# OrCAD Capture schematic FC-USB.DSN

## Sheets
1 INDEX: size A; title: INDEX; rev: 1.1; note: 188Z10031
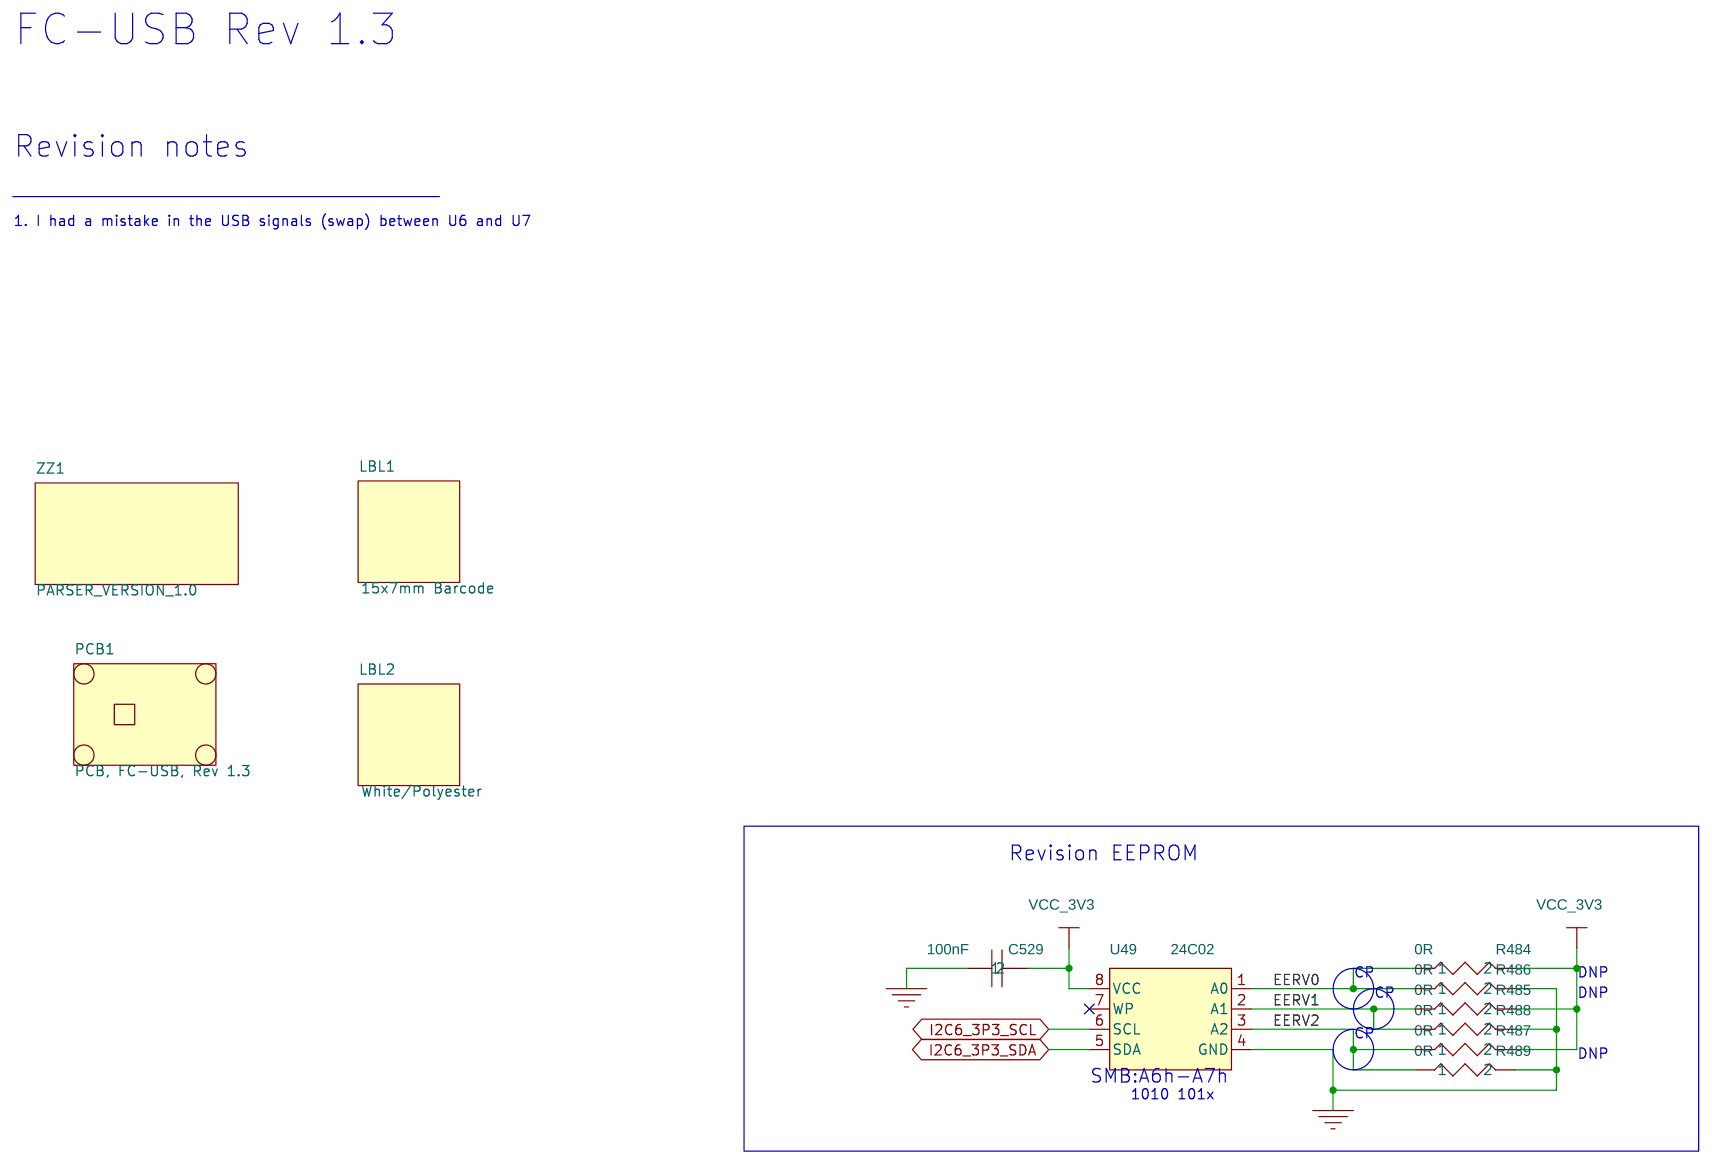
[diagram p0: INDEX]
2 M.2 WIFI+BT: size Custom; title: M.2 WIFI+BT
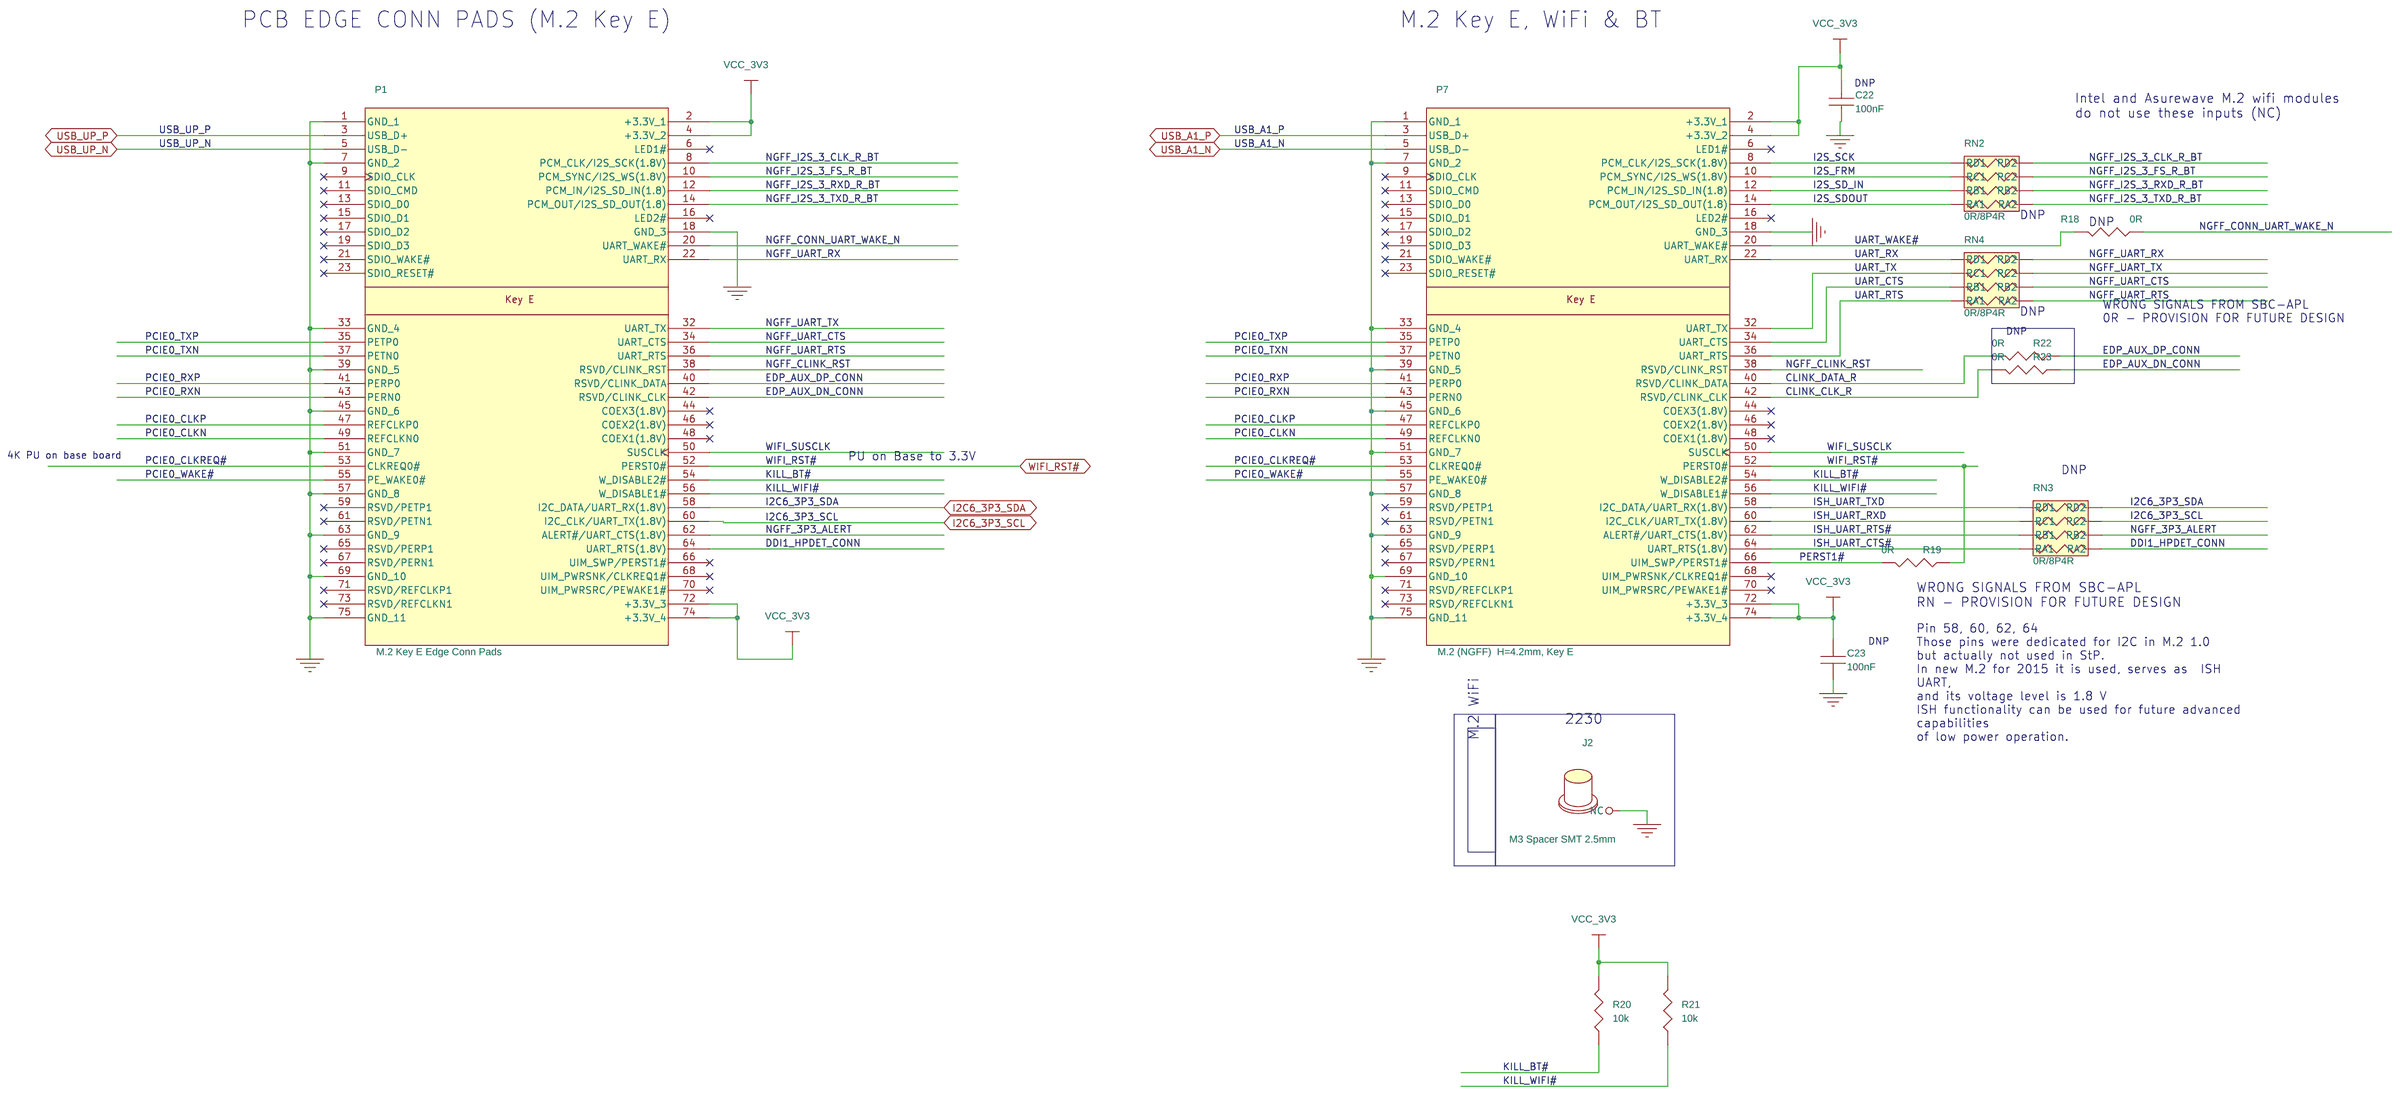
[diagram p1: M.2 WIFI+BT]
3 USB: size Custom; title: USB
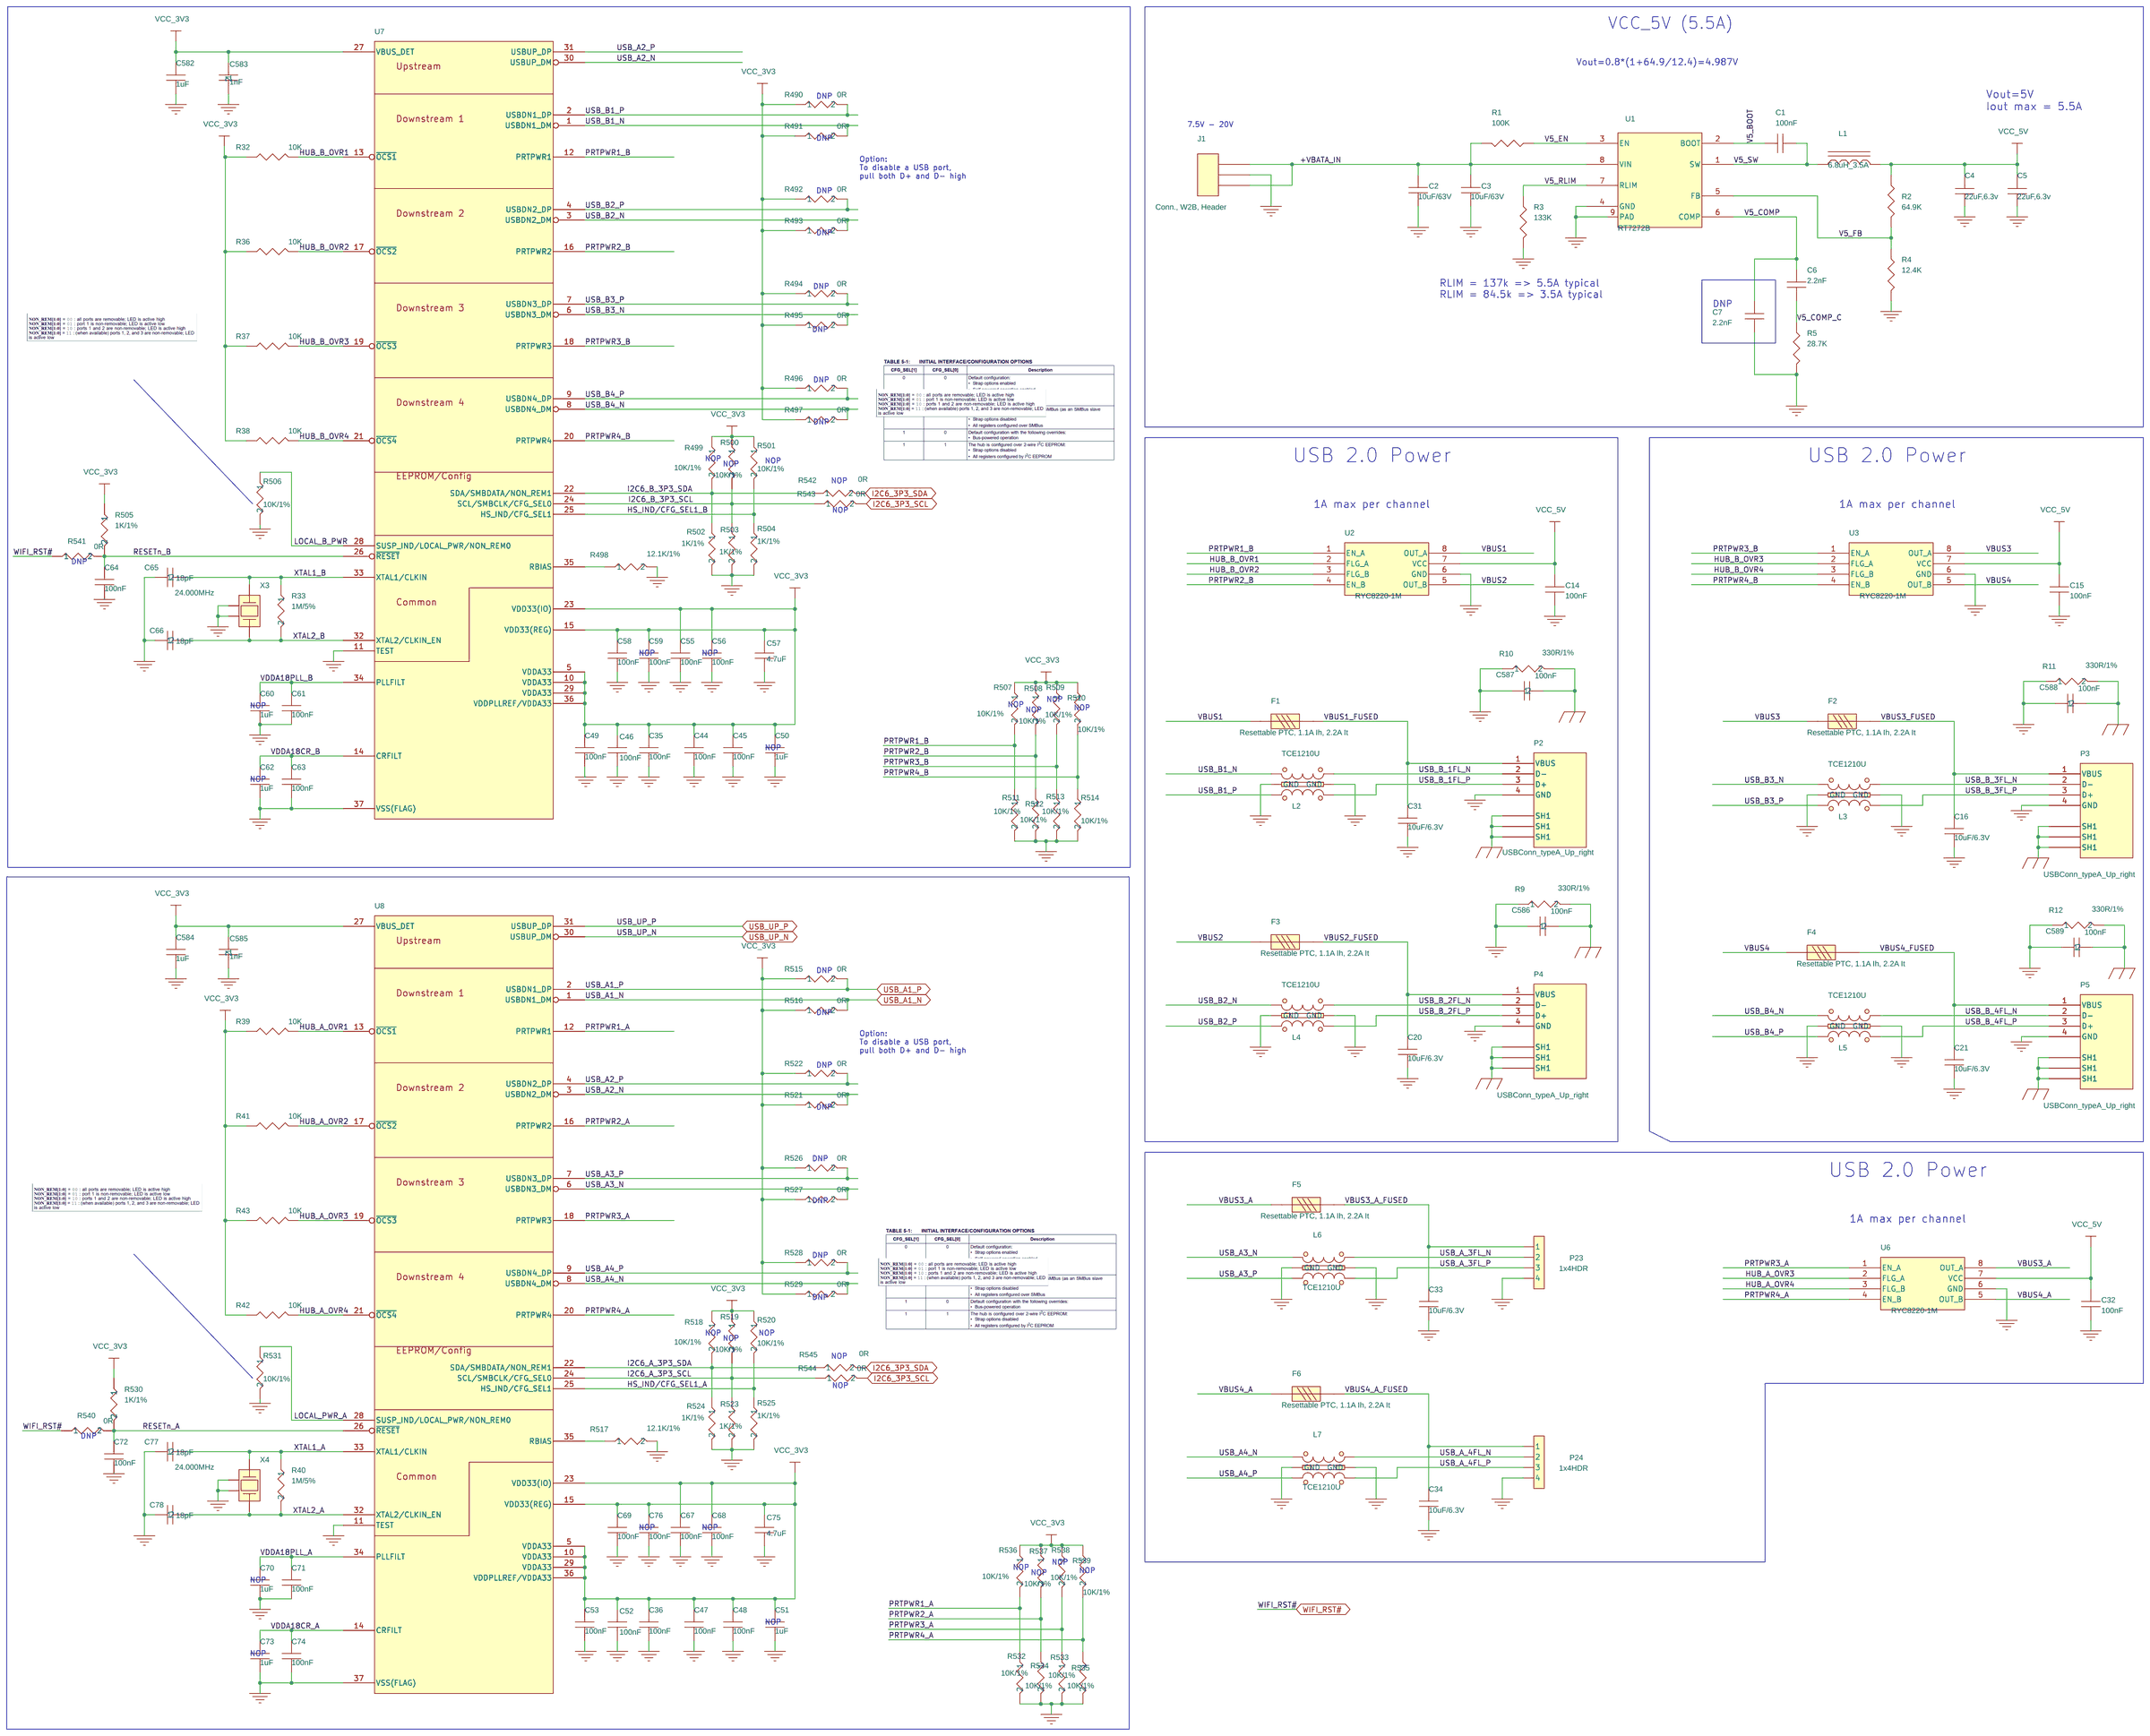
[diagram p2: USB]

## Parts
sheet INDEX
C529  100nF  [RC0402]
LBL1  15x7mm Barcode  [LBL XYU]
LBL2  White/Polyester  [LBL]
PCB1  PCB, FC-USB, Rev 1.3  [NA]
R484  0R  [RC0402]
R485  0R  [RC0402]
R486  0R  [RC0402]
R487  0R  [RC0402]
R488  0R  [RC0402]
R489  0R  [RC0402]
U49  24C02  [MO-229VCED-2]
ZZ1  PARSER_VERSION_1.0
sheet M.2 WIFI+BT
C22  100nF  [RC0402]
C23  100nF  [RC0402]
J2  M3 Spacer SMT 2.5mm  [SpacerM3TAPSM]
P1  M.2 Key E Edge Conn Pads  [EdgeM2keyE]
P7  M.2 (NGFF)  H=4.2mm, Key E  [NGFF67P4HEkeySM]
R18  0R  [RC0402]
R19  0R  [RC0402]
R20  10k  [RC0402]
R21  10k  [RC0402]
R22  0R  [RC0402]
R23  0R  [RC0402]
RN2  0R/8P4R  [RESNET8P0805]
RN3  0R/8P4R  [RESNET8P0805]
RN4  0R/8P4R  [RESNET8P0805]
sheet USB
C1  100nF  [RC0402]
C2  10uF/63V  [C1210H2_5]
C3  10uF/63V  [C1210H2_5]
C4  22uF,6.3v  [RC0603]
C5  22uF,6.3v  [RC0603]
C6  2.2nF  [RC0402]
C7  2.2nF  [RC0402]
C14  100nF  [RC0402]
C15  100nF  [RC0402]
C16  10uF/6.3V  [RC0603]
C20  10uF/6.3V  [RC0603]
C21  10uF/6.3V  [RC0603]
C31  10uF/6.3V  [RC0603]
C32  100nF  [RC0402]
C33  10uF/6.3V  [RC0603]
C34  10uF/6.3V  [RC0603]
C35  100nF  [RC0402]
C36  100nF  [RC0402]
C44  100nF  [RC0402]
C45  100nF  [RC0402]
C46  100nF  [RC0402]
C47  100nF  [RC0402]
C48  100nF  [RC0402]
C49  100nF  [RC0402]
C50  1uF  [RC0402]
C51  1uF  [RC0402]
C52  100nF  [RC0402]
C53  100nF  [RC0402]
C55  100nF  [RC0402]
C56  100nF  [RC0402]
C57  4.7uF  [C0603-08]
C58  100nF  [RC0402]
C59  100nF  [RC0402]
C60  1uF  [RC0402]
C61  100nF  [RC0402]
C62  1uF  [RC0402]
C63  100nF  [RC0402]
C64  100nF  [RC0402]
C65  18pF  [RC0402]
C66  18pF  [RC0402]
C67  100nF  [RC0402]
C68  100nF  [RC0402]
C69  100nF  [RC0402]
C70  1uF  [RC0402]
C71  100nF  [RC0402]
C72  100nF  [RC0402]
C73  1uF  [RC0402]
C74  100nF  [RC0402]
C75  4.7uF  [C0603-08]
C76  100nF  [RC0402]
C77  18pF  [RC0402]
C78  18pF  [RC0402]
C582  1uF  [RC0402]
C583  1nF  [RC0402]
C584  1uF  [RC0402]
C585  1nF  [RC0402]
C586  100nF  [RC0402]
C587  100nF  [RC0402]
C588  100nF  [RC0402]
C589  100nF  [RC0402]
F1  Resettable PTC, 1.1A Ih, 2.2A It  [FUSE-1206]
F2  Resettable PTC, 1.1A Ih, 2.2A It  [FUSE-1206]
F3  Resettable PTC, 1.1A Ih, 2.2A It  [FUSE-1206]
F4  Resettable PTC, 1.1A Ih, 2.2A It  [FUSE-1206]
F5  Resettable PTC, 1.1A Ih, 2.2A It  [FUSE-1206]
F6  Resettable PTC, 1.1A Ih, 2.2A It  [FUSE-1206]
J1  Conn., W2B, Header  [1x3W2B1_25RASM]
L1  6.8uH_3.5A  [IND8_2x8_2]
L2  TCE1210U  [EMI1012-ESD]
L3  TCE1210U  [EMI1012-ESD]
L4  TCE1210U  [EMI1012-ESD]
L5  TCE1210U  [EMI1012-ESD]
L6  TCE1210U  [EMI1012-ESD]
L7  TCE1210U  [EMI1012-ESD]
P2  USBConn_typeA_Up_right  [USB-A-UP-TH]
P3  USBConn_typeA_Up_right  [USB-A-UP-TH]
P4  USBConn_typeA_Up_right  [USB-A-UP-TH]
P5  USBConn_typeA_Up_right  [USB-A-UP-TH]
P23  1x4HDR  [1X4THHDR]
P24  1x4HDR  [1X4THHDR]
R1  100K  [RC0402]
R2  64.9K  [RC0402]
R3  133K  [RC0402]
R4  12.4K  [RC0402]
R5  28.7K  [RC0402]
R9  330R/1%  [RC0402]
R10  330R/1%  [RC0402]
R11  330R/1%  [RC0402]
R12  330R/1%  [RC0402]
R32  10K  [RC0402]
R33  1M/5%  [RC0402]
R36  10K  [RC0402]
R37  10K  [RC0402]
R38  10K  [RC0402]
R39  10K  [RC0402]
R40  1M/5%  [RC0402]
R41  10K  [RC0402]
R42  10K  [RC0402]
R43  10K  [RC0402]
R490  0R  [RC0402]
R491  0R  [RC0402]
R492  0R  [RC0402]
R493  0R  [RC0402]
R494  0R  [RC0402]
R495  0R  [RC0402]
R496  0R  [RC0402]
R497  0R  [RC0402]
R498  12.1K/1%  [RC0402]
R499  10K/1%  [RC0402]
R500  10K/1%  [RC0402]
R501  10K/1%  [RC0402]
R502  1K/1%  [RC0402]
R503  1K/1%  [RC0402]
R504  1K/1%  [RC0402]
R505  1K/1%  [RC0402]
R506  10K/1%  [RC0402]
R507  10K/1%  [RC0402]
R508  10K/1%  [RC0402]
R509  10K/1%  [RC0402]
R510  10K/1%  [RC0402]
R511  10K/1%  [RC0402]
R512  10K/1%  [RC0402]
R513  10K/1%  [RC0402]
R514  10K/1%  [RC0402]
R515  0R  [RC0402]
R516  0R  [RC0402]
R517  12.1K/1%  [RC0402]
R518  10K/1%  [RC0402]
R519  10K/1%  [RC0402]
R520  10K/1%  [RC0402]
R521  0R  [RC0402]
R522  0R  [RC0402]
R523  1K/1%  [RC0402]
R524  1K/1%  [RC0402]
R525  1K/1%  [RC0402]
R526  0R  [RC0402]
R527  0R  [RC0402]
R528  0R  [RC0402]
R529  0R  [RC0402]
R530  1K/1%  [RC0402]
R531  10K/1%  [RC0402]
R532  10K/1%  [RC0402]
R533  10K/1%  [RC0402]
R534  10K/1%  [RC0402]
R535  10K/1%  [RC0402]
R536  10K/1%  [RC0402]
R537  10K/1%  [RC0402]
R538  10K/1%  [RC0402]
R539  10K/1%  [RC0402]
R540  0R  [RC0402]
R541  0R  [RC0402]
R542  0R  [RC0402]
R543  0R  [RC0402]
R544  0R  [RC0402]
R545  0R  [RC0402]
U1  RT7272B  [PSOP-8-2X2]
U2  RYC8220-1M  [SO-8-150]
U3  RYC8220-1M  [SO-8-150]
U6  RYC8220-1M  [SO-8-150]
U7  USB2514Bi  [VQFN (20)]
U8  USB2514Bi  [VQFN (20)]
X3  24.000MHz  [OSC3225]
X4  24.000MHz  [OSC3225]

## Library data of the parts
C529 C586 = 100nF,_10V,_X7R,_10%,_0402: CLABCONF0: =FC-USB
LBL1 = Label_8x8mm_x_3_for_Barcode: CLABCONF0: =FC-USB; P/N: 374P07P14W
LBL2 = Label_white_polyester: CLABCONF0: =FC-USB; P/N: 374F13P20C
PCB1 = SBC-iPC3_rev1.1: CLABCONF0: =FC-USB; P/N: 188C03143
R484 = 0R,_0402_5: CLABCONF0: =FC-USB
R485 R543 = 0R,_0402_4: CLABCONF0: =DNP
R486 R526 = 0R,_0402_3: CLABCONF0: =DNP
R487 = 0R,_0402_2: CLABCONF0: =FC-USB
R488 = 0R,_0402_1: CLABCONF0: =FC-USB
R489 R541 = 0R,_0402: CLABCONF0: =DNP
U49 = 24C02,_serial_EE,_2KB,_I2C_0: CLABCONF0: =FC-USB
ZZ1 = PARSER_VERSION_1.0
C22 C23 = 100nF_0402_25V_0: CLABCONF0: =DNP
J2 = Spacer_SMT,_M2,_4mm: CLABCONF0: =FC-USB; P/N: 383B54510S
P1 = Conn.,_M.2_Key_E_PCIe: CLABCONF0: =FC-USB; P/N: NA2
P7 = Conn.,_M.2_Key_E_PCIe: CLABCONF0: =FC-USB; P/N: 182K06701S
R18 R22 R23 = 0R_0: CLABCONF0: =DNP
R19 = 0R_0: CLABCONF0: =FC-USB
R20 R21 = 1M_,5%,_0402_0: CLABCONF0: =FC-USB; P/N: 161C10021S
RN2-RN4 = RN,0R,8P4R@0805: CLABCONF0: =DNP
C1 = 100nF,_10V,_X7R,_10%,_0402_0: CLABCONF0: =FC-USB; Group: LAN2
C2 C3 = 22uF_25V: CLABCONF0: =FC-USB; P/N: 151E10680S
C4 C5 = 100nF,_10V,_X7R,_10%,_0402_0: CLABCONF0: =FC-USB; P/N: 151B22610S
C6 = 2.2nF,_50V,_X7R,_10%,_0402: CLABCONF0: =FC-USB
C7 = 2_0.2nF,_50V,_X7R,_10%,_0402: CLABCONF0: =DNP
C14 C15 C32 C35 C36 C44-C49 C52 C53 C55 C58 C61 C63 C64 C67 C69 C71 C72 C74 C588 = 100nF,_10V,_X7R,_10%,_0402_1: CLABCONF0: =FC-USB
C16 C20 C21 C31 C33 C34 = 10uF,6.3V,0603,20%X5R: CLABCONF0: =FC-USB; P/N: 151B10610S
C50 C51 C60 C62 C70 C73 = 1uF,X5R,6.3V,0402: CLABCONF0: =DNP
C56 C59 C68 C76 = 100nF,_10V,_X7R,_10%,_0402_1: CLABCONF0: =DNP
C57 C75 = 4.7uF,_6.3V,_X5R,_20%,_0603: CLABCONF0: =FC-USB
C65 = Cap.,_18pF,_50V,_NPO,_5%_2: CLABCONF0: =FC-USB
C66 = Cap.,_18pF,_50V,_NPO,_5%_3: CLABCONF0: =FC-USB
C77 = Cap.,_18pF,_50V,_NPO,_5%: CLABCONF0: =FC-USB
C78 = Cap.,_18pF,_50V,_NPO,_5%_1: CLABCONF0: =FC-USB
C582 C584 = 1uF,X5R,6.3V,0402: CLABCONF0: =FC-USB
C583 = 1nF,10%,_50V,_X7R,_0402: CLABCONF0: =DNP
C585 = 1nF,10%,_50V,_X7R,_0402_1: CLABCONF0: =DNP
C587 = 100nF,_10V,_X7R,_10%,_0402_3: CLABCONF0: =FC-USB
C589 = 100nF,_10V,_X7R,_10%,_0402_2: CLABCONF0: =FC-USB
F1-F6 = Fuse,_0.75A_Ih,_1.5A_It: CLABCONF0: =FC-USB; P/N: 175P22200S
J1 = CON3: CLABCONF0: =FC-USB; P/N: 182E00302S
L1 = IND_6.8uH_3.5A: CLABCONF0: =FC-USB; P/N: 147A6R801S
L2-L7 = ESD_CHOKE_DIFFx2_10: CLABCONF0: =FC-USB; P/N: 142D11801S
P2 = USB_Type_A_Upright_1_1: CLABCONF0: =FC-USB
P3 = USB_Type_A_Upright_1_3: CLABCONF0: =FC-USB
P4 = USB_Type_A_Upright_1: CLABCONF0: =FC-USB
P5 = USB_Type_A_Upright_1_2: CLABCONF0: =FC-USB
P23 = 1x4_HDR,TH_0: CLABCONF0: =FC-USB; P/N: 190C00400
P24 = 1x4_HDR,TH_0_1: CLABCONF0: =FC-USB; P/N: 190C00400
R1 = 100K,_0402_0: CLABCONF0: =FC-USB
R2 = 10.5K_1%,0402: CLABCONF0: =FC-USB; P/N: 161C64921S
R3 = 2.37K_1%,_0402: CLABCONF0: =FC-USB; P/N: 161C13331S
R4 = 2.37K_1%,_0402: CLABCONF0: =FC-USB; P/N: 161C12421S
R5 = 40.2k_1%: CLABCONF0: =FC-USB; P/N: 161C28721S
R9 = 750R,1%,0402_3: CLABCONF0: =FC-USB; P/N: 161C33001S
R10 = 750R,1%,0402_2: CLABCONF0: =FC-USB; P/N: 161C33001S
R11 = 750R,1%,0402: CLABCONF0: =FC-USB; P/N: 161C33001S
R12 = 750R,1%,0402_1: CLABCONF0: =FC-USB; P/N: 161C33001S
R32 R36-R39 R41-R43 = 10K,1%,0402,1_16W_0: CLABCONF0: =FC-USB
R33 = 1M_,5%,_0402_1: CLABCONF0: =FC-USB
R40 = 1M_,5%,_0402: CLABCONF0: =FC-USB
R490 = 0R,_0402_16: CLABCONF0: =DNP
R491 = 0R,_0402_7: CLABCONF0: =DNP
R492 = 0R,_0402_11: CLABCONF0: =DNP
R493 = 0R,_0402_1: CLABCONF0: =DNP
R494 = 0R,_0402_6: CLABCONF0: =DNP
R495 = 0R,_0402_21: CLABCONF0: =DNP
R496 = 0R,_0402_18: CLABCONF0: =DNP
R497 = 0R,_0402_13: CLABCONF0: =DNP
R498 = 12.1K,1%,0402,1_16W: CLABCONF0: =FC-USB
R499 = 10K,1%,0402,1_16W_14: CLABCONF0: =DNP
R500 = 10K,1%,0402,1_16W_9: CLABCONF0: =DNP
R501 = 10K,1%,0402,1_16W_13: CLABCONF0: =DNP
R502 = 1K,1%,0402,1_16W_7: CLABCONF0: =FC-USB
R503 = 1K,1%,0402,1_16W_4: CLABCONF0: =FC-USB
R504 = 1K,1%,0402,1_16W_1: CLABCONF0: =FC-USB
R505 = 1K,1%,0402,1_16W_3: CLABCONF0: =FC-USB
R506 = 10K,1%,0402,1_16W_15: CLABCONF0: =FC-USB
R507 = 10K,1%,0402,1_16W_3: CLABCONF0: =DNP
R508 = 10K,1%,0402,1_16W_18: CLABCONF0: =DNP
R509 = 10K,1%,0402,1_16W_5: CLABCONF0: =DNP
R510 = 10K,1%,0402,1_16W_16: CLABCONF0: =DNP
R511 = 10K,1%,0402,1_16W_7: CLABCONF0: =FC-USB
R512 = 10K,1%,0402,1_16W_1: CLABCONF0: =FC-USB
R513 = 10K,1%,0402,1_16W_17: CLABCONF0: =FC-USB
R514 = 10K,1%,0402,1_16W: CLABCONF0: =FC-USB
R515 = 0R,_0402_8: CLABCONF0: =DNP
R516 = 0R,_0402_5: CLABCONF0: =DNP
R517 = 12.1K,1%,0402,1_16W_1: CLABCONF0: =FC-USB
R518 = 10K,1%,0402,1_16W_4: CLABCONF0: =DNP
R519 = 10K,1%,0402,1_16W_2: CLABCONF0: =DNP
R520 = 10K,1%,0402,1_16W_20: CLABCONF0: =DNP
R521 = 0R,_0402_9: CLABCONF0: =DNP
R522 = 0R,_0402_19: CLABCONF0: =DNP
R523 = 1K,1%,0402,1_16W: CLABCONF0: =FC-USB
R524 = 1K,1%,0402,1_16W_5: CLABCONF0: =FC-USB
R525 = 1K,1%,0402,1_16W_2: CLABCONF0: =FC-USB
R527 = 0R,_0402_17: CLABCONF0: =DNP
R528 = 0R,_0402_12: CLABCONF0: =DNP
R529 = 0R,_0402_10: CLABCONF0: =DNP
R530 = 1K,1%,0402,1_16W_6: CLABCONF0: =FC-USB
R531 = 10K,1%,0402,1_16W_12: CLABCONF0: =FC-USB
R532 = 10K,1%,0402,1_16W_11: CLABCONF0: =FC-USB
R533 = 10K,1%,0402,1_16W_8: CLABCONF0: =FC-USB
R534 = 10K,1%,0402,1_16W_21: CLABCONF0: =FC-USB
R535 = 10K,1%,0402,1_16W_6: CLABCONF0: =FC-USB
R536 = 10K,1%,0402,1_16W_10: CLABCONF0: =DNP
R537 = 10K,1%,0402,1_16W_23: CLABCONF0: =DNP
R538 = 10K,1%,0402,1_16W_22: CLABCONF0: =DNP
R539 = 10K,1%,0402,1_16W_19: CLABCONF0: =DNP
R540 = 0R,_0402_20: CLABCONF0: =DNP
R542 = 0R,_0402_15: CLABCONF0: =DNP
R544 = 0R,_0402_2: CLABCONF0: =DNP
R545 = 0R,_0402_14: CLABCONF0: =DNP
U1 = RT7272B,Converter,3A,36V: CLABCONF0: =FC-USB; P/N: 123V30000S
U2 U3 U6 = TMP_164704: CLABCONF0: =FC-USB
U7 U8 = USB2514Bi: CLABCONF0: =FC-USB; P/N: 116A25140S
X3 X4 = XTAL,24.000Mhz,100ppm,Ind,3x5mm: CLABCONF0: =FC-USB; P/N: 141B24604I

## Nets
+VBATA_IN: C2.1 C3.1 J1.1 J1.3 R1.2 U1.8(VIN)
GND: C2.2 C3.2 C4.1 C5.1 C7.2 C14.2 C15.2 C16.2 C20.2 C21.2 C22.1 C23.1 C31.2 C32.2 C33.2 C34.2 C35.2 C36.2 C44.2 C45.2 C46.2 C47.2 C48.2 C49.2 C50.2 C51.2 C52.2 C53.2 C55.2 C56.2 C57.1 C58.2 C59.2 C60.2 C61.2 C62.2 C63.2 C64.2 C65.1 C66.1 C67.2 C68.2 C69.2 C70.2 C71.2 C72.2 C73.2 C74.2 C75.1 C76.2 C77.1 C78.1 C529.1 C582.2 C583.2 C584.2 C585.2 C586.1 C587.1 C588.1 C589.1 J1.2 J2.NC L2.5(GND) L2.6(GND) L3.5(GND) L3.6(GND) L4.5(GND) L4.6(GND) L5.5(GND) L5.6(GND) L6.5(GND) L6.6(GND) L7.5(GND) L7.6(GND) P1.1(GND) P1.7(GND_2) P1.18(GND_3) P1.33(GND_4) P1.39(GND_5) P1.45(GND_6) P1.51(GND_7) P1.57(GND_8) P1.63(GND_9) P1.69(GND_10) P1.75(GND_11) P2.4(GND) P3.4(GND) P4.4(GND) P5.4(GND) P7.1(GND) P7.7(GND_2) P7.18(GND_3) P7.33(GND_4) P7.39(GND_5) P7.45(GND_6) P7.51(GND_7) P7.57(GND_8) P7.63(GND_9) P7.69(GND_10) P7.75(GND_11) P23.4 P24.4 R3.2 R4.2 R5.2 R9.1 R10.1 R11.1 R12.1 R486.2 R488.2 R489.2 R498.2 R502.2 R503.2 R504.2 R506.2 R511.2 R512.2 R513.2 R514.2 R517.2 R523.2 R524.2 R525.2 R531.2 R532.2 R533.2 R534.2 R535.2 U1.4(GND) U1.9(PAD) U2.6(GND) U3.6(GND) U6.6(GND) U7.11(TEST) U7.37(VSS(FLAG)) U8.11(TEST) U8.37(VSS(FLAG)) U49.4(GND) X3.2 X3.4 X4.2 X4.4
GND_EARTH: C586.2 C587.2 C588.2 C589.2 P2.SH1 P3.SH1 P4.SH1 P5.SH1 R9.2 R10.2 R11.2 R12.2
V5_BOOT: C1.1 U1.2(BOOT)
V5_COMP: C6.1 C7.1 U1.6(COMP)
V5_COMP_C: C6.2 R5.1
V5_EN: R1.1 U1.3(EN)
V5_FB: R2.2 R4.1 U1.5(FB)
V5_RLIM: R3.1 U1.7(RLIM)
V5_SW: C1.2 L1.1 U1.1(SW)
VBUS1: F1.2 U2.8(OUT_A)
VBUS1_FUSED: C31.1 F1.1 P2.1(VBUS)
VBUS2: F3.2 U2.5(OUT_B)
VBUS2_FUSED: C20.1 F3.1 P4.1(VBUS)
VBUS3: F2.2 U3.8(OUT_A)
VBUS3_A: F5.2 U6.8(OUT_A)
VBUS3_A_FUSED: C33.1 F5.1 P23.1
VBUS3_FUSED: C16.1 F2.1 P3.1(VBUS)
VBUS4: F4.2 U3.5(OUT_B)
VBUS4_A: F6.2 U6.5(OUT_B)
VBUS4_A_FUSED: C34.1 F6.1 P24.1
VBUS4_FUSED: C21.1 F4.1 P5.1(VBUS)
VCC_3V3: C22.2 C23.2 C35.1 C36.1 C44.1 C45.1 C46.1 C47.1 C48.1 C49.1 C50.1 C51.1 C52.1 C53.1 C55.1 C56.1 C57.2 C58.1 C59.1 C67.1 C68.1 C69.1 C75.2 C76.1 C529.2 C582.1 C583.1 C584.1 C585.1 P1.2(+3.3V_1) P1.4(+3.3V_2) P1.72(+3.3V_3) P1.74(+3.3V_4) P7.2(+3.3V_1) P7.4(+3.3V_2) P7.72(+3.3V_3) P7.74(+3.3V_4) R20.2 R21.2 R32.1 R36.1 R37.1 R38.1 R39.1 R41.1 R42.1 R43.1 R484.2 R485.2 R487.2 R490.1 R491.1 R492.1 R493.1 R494.1 R495.1 R496.1 R497.1 R499.1 R500.1 R501.1 R505.1 R507.1 R508.1 R509.1 R510.1 R515.1 R516.1 R518.1 R519.1 R520.1 R521.1 R522.1 R526.1 R527.1 R528.1 R529.1 R530.1 R536.1 R537.1 R538.1 R539.1 U7.5(VDDA33) U7.10(VDDA33) U7.15(VDD33(REG)) U7.23(VDD33(IO)) U7.27(VBUS_DET) U7.29(VDDA33) U7.36(VDDPLLREF/VDDA33) U8.5(VDDA33) U8.10(VDDA33) U8.15(VDD33(REG)) U8.23(VDD33(IO)) U8.27(VBUS_DET) U8.29(VDDA33) U8.36(VDDPLLREF/VDDA33) U49.8(VCC)
VCC_5V: C4.2 C5.2 C14.1 C15.1 C32.1 L1.2 R2.1 U2.7(VCC) U3.7(VCC) U6.7(VCC)
VDDA18CR_A: C73.1 C74.1 U8.14(CRFILT)
VDDA18CR_B: C62.1 C63.1 U7.14(CRFILT)
VDDA18PLL_A: C70.1 C71.1 U8.34(PLLFILT)
VDDA18PLL_B: C60.1 C61.1 U7.34(PLLFILT)
CLINK_CLK_R: P7.42(RSVD/CLINK_CLK) R23.2
CLINK_DATA_R: P7.40(RSVD/CLINK_DATA) R22.2
DDI1_HPDET_CONN: P1.64(UART_RTS(1.8V)) RN3.8(RA2)
EDP_AUX_DN_CONN: P1.42(RSVD/CLINK_CLK) R23.1
EDP_AUX_DP_CONN: P1.40(RSVD/CLINK_DATA) R22.1
EERV0: R484.1 R486.1 U49.1(A0)
EERV1: R485.1 R488.1 U49.2(A1)
EERV2: R487.1 R489.1 U49.3(A2)
HS_IND/CFG_SEL1_A: R520.2 R525.1 U8.25(HS_IND/CFG_SEL1)
HS_IND/CFG_SEL1_B: R501.2 R504.1 U7.25(HS_IND/CFG_SEL1)
HUB_A_OVR1: R39.2 U8.13(~{OCS1})
HUB_A_OVR2: R41.2 U8.17(~{OCS2})
HUB_A_OVR3: R43.2 U6.2(FLG_A) U8.19(~{OCS3})
HUB_A_OVR4: R42.2 U6.3(FLG_B) U8.21(~{OCS4})
HUB_B_OVR1: R32.2 U2.2(FLG_A) U7.13(~{OCS1})
HUB_B_OVR2: R36.2 U2.3(FLG_B) U7.17(~{OCS2})
HUB_B_OVR3: R37.2 U3.2(FLG_A) U7.19(~{OCS3})
HUB_B_OVR4: R38.2 U3.3(FLG_B) U7.21(~{OCS4})
I2C6_3P3_SCL: P1.60(I2C_CLK/UART_TX(1.8V)) R543.2 R544.2 RN3.6(RC2) U49.6(SCL)
I2C6_3P3_SDA: P1.58(I2C_DATA/UART_RX(1.8V)) R542.2 R545.2 RN3.5(RD2) U49.5(SDA)
I2C6_A_3P3_SCL: R519.2 R523.1 R544.1 U8.24(SCL/SMBCLK/CFG_SEL0)
I2C6_A_3P3_SDA: R518.2 R524.1 R545.1 U8.22(SDA/SMBDATA/NON_REM1)
I2C6_B_3P3_SCL: R500.2 R503.1 R543.1 U7.24(SCL/SMBCLK/CFG_SEL0)
I2C6_B_3P3_SDA: R499.2 R502.1 R542.1 U7.22(SDA/SMBDATA/NON_REM1)
I2S_FRM: P7.10(PCM_SYNC/I2S_WS(1.8V)) RN2.3(RC1)
I2S_SCK: P7.8(PCM_CLK/I2S_SCK(1.8V)) RN2.4(RD1)
I2S_SD_IN: P7.12(PCM_IN/I2S_SD_IN(1.8)) RN2.2(RB1)
I2S_SDOUT: P7.14(PCM_OUT/I2S_SD_OUT(1.8)) RN2.1(RA1)
ISH_UART_CTS#: P7.64(UART_RTS(1.8V)) RN3.1(RA1)
ISH_UART_RTS#: P7.62(ALERT#/UART_CTS(1.8V)) RN3.2(RB1)
ISH_UART_RXD: P7.60(I2C_CLK/UART_TX(1.8V)) RN3.3(RC1)
ISH_UART_TXD: P7.58(I2C_DATA/UART_RX(1.8V)) RN3.4(RD1)
KILL_BT#: P1.54(W_DISABLE2#) P7.54(W_DISABLE2#) R20.1
KILL_WIFI#: P1.56(W_DISABLE1#) P7.56(W_DISABLE1#) R21.1
LOCAL_B_PWR: R506.1 U7.28(SUSP_IND/LOCAL_PWR/NON_REM0)
LOCAL_PWR_A: R531.1 U8.28(SUSP_IND/LOCAL_PWR/NON_REM0)
NGFF_3P3_ALERT: P1.62(ALERT#/UART_CTS(1.8V)) RN3.7(RB2)
NGFF_CLINK_RST: P1.38(RSVD/CLINK_RST) P7.38(RSVD/CLINK_RST)
NGFF_CONN_UART_WAKE_N: P1.20(UART_WAKE#) R18.1
NGFF_I2S_3_CLK_R_BT: P1.8(PCM_CLK/I2S_SCK(1.8V)) RN2.5(RD2)
NGFF_I2S_3_FS_R_BT: P1.10(PCM_SYNC/I2S_WS(1.8V)) RN2.6(RC2)
NGFF_I2S_3_RXD_R_BT : P1.12(PCM_IN/I2S_SD_IN(1.8)) RN2.7(RB2)
NGFF_I2S_3_TXD_R_BT: P1.14(PCM_OUT/I2S_SD_OUT(1.8)) RN2.8(RA2)
NGFF_UART_CTS: P1.34(UART_CTS) RN4.7(RB2)
NGFF_UART_RTS: P1.36(UART_RTS) RN4.8(RA2)
NGFF_UART_RX: P1.22(UART_RX) RN4.5(RD2)
NGFF_UART_TX: P1.32(UART_TX) RN4.6(RC2)
PCIE0_CLKN: P1.49(REFCLKN0) P7.49(REFCLKN0)
PCIE0_CLKP: P1.47(REFCLKP0) P7.47(REFCLKP0)
PCIE0_CLKREQ#: P1.53(CLKREQ0#) P7.53(CLKREQ0#)
PCIE0_RXN: P1.43(PERN0) P7.43(PERN0)
PCIE0_RXP: P1.41(PERP0) P7.41(PERP0)
PCIE0_TXN: P1.37(PETN0) P7.37(PETN0)
PCIE0_TXP: P1.35(PETP0) P7.35(PETP0)
PCIE0_WAKE#: P1.55(PE_WAKE0#) P7.55(PE_WAKE0#)
PERST1#: P7.66(UIM_SWP/PERST1#) R19.2
PRTPWR1_A: R532.1 R536.2 U8.12(PRTPWR1)
PRTPWR1_B: R507.2 R511.1 U2.1(EN_A) U7.12(PRTPWR1)
PRTPWR2_A: R534.1 R537.2 U8.16(PRTPWR2)
PRTPWR2_B: R508.2 R512.1 U2.4(EN_B) U7.16(PRTPWR2)
PRTPWR3_A: R533.1 R538.2 U6.1(EN_A) U8.18(PRTPWR3)
PRTPWR3_B: R509.2 R513.1 U3.1(EN_A) U7.18(PRTPWR3)
PRTPWR4_A: R535.1 R539.2 U6.4(EN_B) U8.20(PRTPWR4)
PRTPWR4_B: R510.2 R514.1 U3.4(EN_B) U7.20(PRTPWR4)
RESETn_A: C72.1 R530.2 R540.2 U8.26(~{RESET})
RESETn_B: C64.1 R505.2 R541.2 U7.26(~{RESET})
UART_CTS: P7.34(UART_CTS) RN4.2(RB1)
UART_RTS: P7.36(UART_RTS) RN4.1(RA1)
UART_RX: P7.22(UART_RX) RN4.4(RD1)
UART_TX: P7.32(UART_TX) RN4.3(RC1)
UART_WAKE#: P7.20(UART_WAKE#) R18.2
USB_A1_N: P7.5(USB_D-) R516.2 U8.1(USBDN1_DM)
USB_A1_P: P7.3(USB_D+) R515.2 U8.2(USBDN1_DP)
USB_A2_N: R521.2 U7.30(USBUP_DM) U8.3(USBDN2_DM)
USB_A2_P: R522.2 U7.31(USBUP_DP) U8.4(USBDN2_DP)
USB_A3_N: L6.4 R527.2 U8.6(USBDN3_DM)
USB_A3_P: L6.3 R526.2 U8.7(USBDN3_DP)
USB_A4_N: L7.4 R529.2 U8.8(USBDN4_DM)
USB_A4_P: L7.3 R528.2 U8.9(USBDN4_DP)
USB_A_3FL_N: L6.1 P23.2
USB_A_3FL_P: L6.2 P23.3
USB_A_4FL_N: L7.1 P24.2
USB_A_4FL_P: L7.2 P24.3
USB_B1_N: L2.3 R491.2 U7.1(USBDN1_DM)
USB_B1_P: L2.4 R490.2 U7.2(USBDN1_DP)
USB_B2_N: L4.3 R493.2 U7.3(USBDN2_DM)
USB_B2_P: L4.4 R492.2 U7.4(USBDN2_DP)
USB_B3_N: L3.3 R495.2 U7.6(USBDN3_DM)
USB_B3_P: L3.4 R494.2 U7.7(USBDN3_DP)
USB_B4_N: L5.3 R497.2 U7.8(USBDN4_DM)
USB_B4_P: L5.4 R496.2 U7.9(USBDN4_DP)
USB_B_1FL_N: L2.2 P2.2(D-)
USB_B_1FL_P: L2.1 P2.3(D+)
USB_B_2FL_N: L4.2 P4.2(D-)
USB_B_2FL_P: L4.1 P4.3(D+)
USB_B_3FL_N: L3.2 P3.2(D-)
USB_B_3FL_P: L3.1 P3.3(D+)
USB_B_4FL_N: L5.2 P5.2(D-)
USB_B_4FL_P: L5.1 P5.3(D+)
USB_UP_N: P1.5(USB_D-) U8.30(USBUP_DM)
USB_UP_P: P1.3(USB_D+) U8.31(USBUP_DP)
WIFI_RST#: P1.52(PERST0#) P7.52(PERST0#) R19.1 R540.1 R541.1
WIFI_SUSCLK: P1.50(SUSCLK) P7.50(SUSCLK)
XTAL1_A: C77.2 R40.1 U8.33(XTAL1/CLKIN) X4.1
XTAL1_B: C65.2 R33.1 U7.33(XTAL1/CLKIN) X3.1
XTAL2_A: C78.2 R40.2 U8.32(XTAL2/CLKIN_EN) X4.3
XTAL2_B: C66.2 R33.2 U7.32(XTAL2/CLKIN_EN) X3.3
N16821056: R498.1 U7.35(RBIAS)
N16826729: R517.1 U8.35(RBIAS)

Not connected (* = marked no-connect by the designer): P1 6(LED1#)* 9(SDIO_CLK)* 11(SDIO_CMD)* 13(SDIO_D0)* 15(SDIO_D1)* 16(LED2#)* 17(SDIO_D2)* 19(SDIO_D3)* 21(SDIO_WAKE#)* 23(SDIO_RESET#)* 44(COEX3(1.8V))* 46(COEX2(1.8V))* 48(COEX1(1.8V))* 59(RSVD/PETP1)* 61(RSVD/PETN1)* 65(RSVD/PERP1)* 66(UIM_SWP/PERST1#)* 67(RSVD/PERN1)* 68(UIM_PWRSNK/CLKREQ1#)* 70(UIM_PWRSRC/PEWAKE1#)* 71(RSVD/REFCLKP1)* 73(RSVD/REFCLKN1)*; P7 6(LED1#)* 9(SDIO_CLK)* 11(SDIO_CMD)* 13(SDIO_D0)* 15(SDIO_D1)* 16(LED2#)* 17(SDIO_D2)* 19(SDIO_D3)* 21(SDIO_WAKE#)* 23(SDIO_RESET#)* 44(COEX3(1.8V))* 46(COEX2(1.8V))* 48(COEX1(1.8V))* 59(RSVD/PETP1)* 61(RSVD/PETN1)* 65(RSVD/PERP1)* 67(RSVD/PERN1)* 68(UIM_PWRSNK/CLKREQ1#)* 70(UIM_PWRSRC/PEWAKE1#)* 71(RSVD/REFCLKP1)* 73(RSVD/REFCLKN1)*; U49 7(WP)*

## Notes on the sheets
sheet 1
- FC-USB Rev 1.3
- Revision notes
- 1. I had a mistake in the USB signals (swap) between U6 and U7
- Revision EEPROM
- CP
- DNP
- CP
- DNP
- CP
- DNP
- SMB:A6h-A7h
- 1010 101x
sheet 2
- PCB EDGE CONN PADS (M.2 Key E)
- M.2 Key E, WiFi & BT
- DNP
- Intel and Asurewave M.2 wifi modules
  do not use these inputs (NC)
- DNP
- DNP
- WRONG SIGNALS FROM SBC-APL
  0R - PROVISION FOR FUTURE DESIGN
- DNP
- DNP
- 4K PU on base board
- PU on Base to 3.3V
- DNP
- WRONG SIGNALS FROM SBC-APL
  RN - PROVISION FOR FUTURE DESIGN
- Pin 58, 60, 62, 64
  Those pins were dedicated for I2C in M.2 1.0
  but actually not used in StP.
  In new M.2 for 2015 it is used, serves as  ISH
  UART,
  and its voltage level is 1.8 V
  ISH functionality can be used for future advanced
  capabilities
  of low power operation.
- DNP
- 2230
- M.2 WiFi
sheet 3
- VCC_5V (5.5A)
- Vout=0.8*(1+64.9/12.4)=4.987V
- Vout=5V
  Iout max = 5.5A
- DNP
- 7.5V - 20V
- DNP
- Option:
  To disable a USB port,
  pull both D+ and D- high
- DNP
- DNP
- DNP
- RLIM = 137k => 5.5A typical
  RLIM = 84.5k => 3.5A typical
- DNP
- DNP
- DNP
- DNP
- USB 2.0 Power
- USB 2.0 Power
- NOP
- NOP
- NOP
- NOP
- 1A max per channel
- 1A max per channel
- NOP
- DNP
- NOP
- NOP
- NOP
- NOP
- NOP
- NOP
- NOP
- NOP
- NOP
- DNP
- DNP
- Option:
  To disable a USB port,
  pull both D+ and D- high
- DNP
- DNP
- DNP
- USB 2.0 Power
- DNP
- 1A max per channel
- DNP
- DNP
- NOP
- NOP
- NOP
- NOP
- NOP
- DNP
- NOP
- NOP
- NOP
- NOP
- NOP
- NOP
- NOP
- NOP
- NOP
